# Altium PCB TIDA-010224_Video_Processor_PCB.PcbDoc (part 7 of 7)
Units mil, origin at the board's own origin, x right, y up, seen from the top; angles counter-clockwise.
Board outline 2355.46 x 4164 mil, 10 copper layers (L1-Top Layer, L2-GND, L3-SIG1, L4-GND, L5-PWR, L6-PWR, L7-GND, L8-SIG2, L9-GND, L10-Bottom Layer), stack 62.2 mil thick; 508 components, 274 nets, 3619 pads, 705 vias.
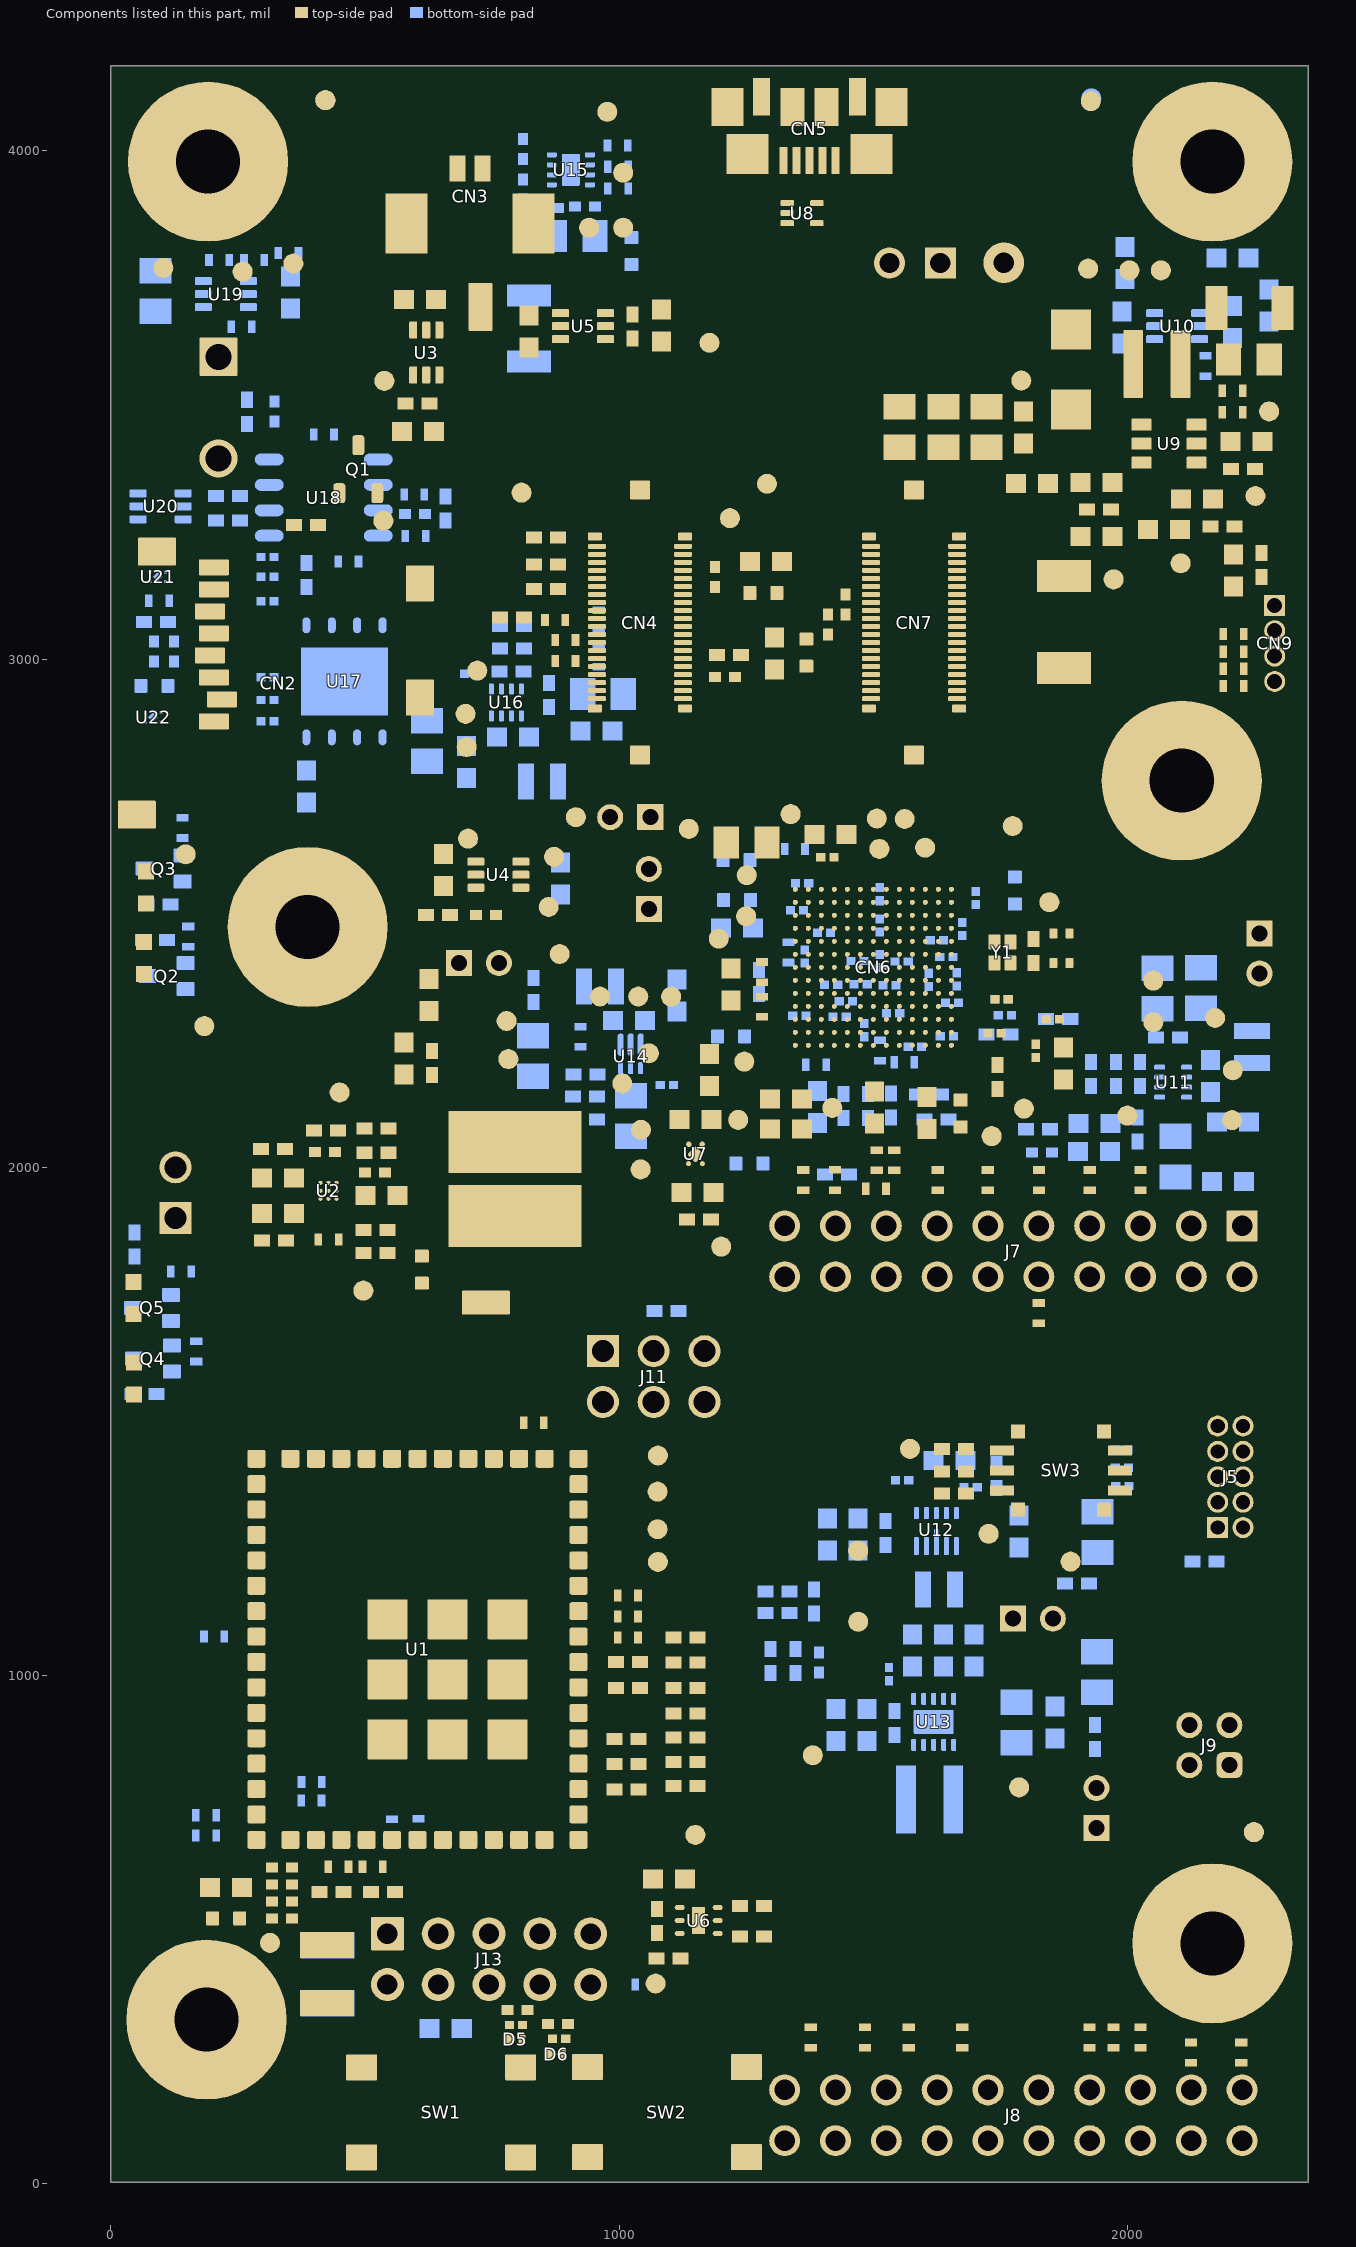
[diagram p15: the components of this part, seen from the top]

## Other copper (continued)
L10-Bottom Layer:
  pour cut-out: 1433.94,2308.27 1430.1,2308.27 1429.23,2307.4 1429.23,2287.84 1431.27,2285.8 1432.85,2285.8 1434.59,2287.54 1434.59,2307.61
  pour cut-out: 1440.91,2370.25 1442.16,2369 1442.16,2317.12 1442.79,2316.49 1442.79,2316.07 1444.13,2314.73 1445.94,2314.73 1445.94,2334.56 1451.6,2340.22 1451.6,2367.41 1448.01,2371 1441.66,2371
  pour cut-out: 1419.62,2368.71 1419.62,2347.59 1418.6,2346.57 1415.64,2346.57 1414.79,2347.42 1414.79,2366.6 1410.43,2370.96 1391.79,2370.96 1387.72,2375.03 1387.72,2393.4 1402,2407.68 1433.91,2407.68 1435.21,2406.39 1433.81,2404.99 1433.81,2375.69 1426.6,2375.69
  pour cut-out: 579.84,2823 579.84,2843.34 612.5,2876 732.77,2876 735,2873.77 735,2864.26 730.74,2860 677.37,2860 674.33,2856.96 674.33,2834.55 666.78,2827 583.84,2827
  pour cut-out: 2056,2073.92 1995.49,2073.92 1994.18,2072.62 1994.18,2004.71 1993.6,2004.14 1833.02,2004.14 1831,2006.16 1831,2102.9 1837,2108.9 1927.51,2108.9 1931.19,2112.57 1931.19,2128.64 1936.37,2133.82 1936.37,2134.51 2050.24,2134.51 2056,2128.75 2055.63,2128.37 2055.63,2074.11
  pour cut-out: 1774.61,2031.93 1731.71,2031.93 1731,2031.21 1728.54,2033.67 1728.54,2061.54 1733.88,2066.88 1762.82,2066.88 1774.61,2055.09
  pour cut-out: 1323.95,2286.36 1316.61,2279.01 1316.61,2139.25 1336.36,2119.5 1449.96,2119.5 1458.46,2128 1477.46,2128 1482,2132.54 1476.46,2138.08 1476.46,2195 1488.19,2206.72 1525.53,2206.72 1532.81,2214 1531.61,2215.2 1531.61,2238.66 1528,2242.28 1527.72,2242 1448.18,2242 1424.18,2266 1400.35,2266 1379.99,2286.36
  pour cut-out: 1816.63,2272.53 1816.63,2224.1 1826.73,2214 1928,2214 1928,2328.03 1924.66,2331.37 1818.37,2331.37 1812,2325 1812,2277.16
  pour cut-out: 412.54,3801.87 412.54,3843.46 402.39,3853.61 275.83,3853.61 261.19,3838.97 261.19,3823.68 261.87,3823 283.23,3823 306.3,3846.07 358.2,3846.07 361.73,3842.54 361.73,3827.37 387.04,3827.37
  pour cut-out: 254.54,3726 210.49,3726 209.95,3725.45 209.95,3764.55 211.22,3763.28 247.01,3763.28 250.73,3759.56 250.73,3729 251.54,3729
  pour cut-out: 1550.84,1045.31 1725.36,1045.31 1725.36,989.94 1554.8,989.94 1554,989.14 1551,992.14 1551,1045
  pour cut-out: 1373,1145.59 1373,1068.76 1383.86,1057.91 1383.86,987.14 1384,987 1383.21,986.21 1371.37,986.21 1366.65,981.48 1258.09,981.48 1253,986.57 1253,1135.53 1264.27,1146.8 1372.99,1146.8
  pour cut-out: 1980.13,2286.52 2005.25,2261.4 2005.25,2185.54 2001.85,2182.14 1951.93,2182.14 1942,2192.07 1942,2248.4
  pour cut-out: 1545,2182 1635.24,2182 1642.24,2175 1642.24,2165.29 1636.46,2159.51 1615.7,2159.51 1610.13,2153.94 1610.13,2103.75 1600.38,2094 1556.81,2094 1544,2106.81 1544,2181
  pour cut-out: 223.01,2536.07 228.58,2530.5 228.58,2384.58 221,2377 26,2377 15,2388 15,2522.37 28.71,2536.07
  pour cut-out: 1164.7,1046.66 1164.7,1126.3 1143,1148 1143,1158.33 1074.33,1158.33 1047.24,1131.24 1047.24,729 1066.56,709.69 1187.61,709.69 1209.63,731.71 1209.63,1033.96 1196.93,1046.66
  pour cut-out: 1561.72,2083 1713.84,2083 1725.78,2071.06 1725.78,2004.26 1671.96,1950.43 1671.96,1904 1664,1896.04 1664,1895.12 1582.05,1895.12 1553.17,1924 1537.94,1924 1537.94,2059.58 1560.72,2082.36
  pour cut-out: 1126.59,2036.55 1126.59,1997.63 1096.8,1967.84 1096.8,1830.26 1046,1779.46 1046,1662.4 1063.4,1645 1242.53,1645 1255,1657.47 1255,1885.41 1296.53,1926.94 1376.94,1926.94 1381.82,1931.82 1381.82,1963.48 1373.15,1972.15 1277.35,1972.15 1265,1984.5 1265,2026.52 1237.85,2053.66 1143.7,2053.66
  pour cut-out: 1129,2035.6 1171.31,2035.6 1180.08,2026.83 1284.93,2026.83 1293.7,2035.6 1293.7,2184.63 1282.33,2196 1277.33,2191 1179.82,2191 1179.82,2162.13 1126.59,2108.9 1126.59,2036.55
  pour cut-out: 66,1836.02 171.01,1836.02 175,1832.03 175,1757.21 164.76,1746.97 78.62,1746.97 64.9,1760.69 64.9,1835.7 65.81,1836.61
  pour cut-out: 96.07,1723.24 96.07,1579.45 113,1562.53 113,1512.9 108.79,1508.69 22.31,1508.69 19,1512 19,1718 24.24,1723.24
  pour cut-out: 2126.96,3664.47 2070.53,3664.47 2050.06,3644 2037.84,3656.22 2011.62,3656.22 2003.37,3664.47 1966.53,3664.47 1962,3669 1962,3753.57 1975.43,3767 2026.95,3767 2077.95,3716 2098.72,3716 2118.46,3696.26 2118.46,3672.97 2126.96,3664.47
  pour cut-out: 383.5,3462 454.5,3462 454.5,3347.05 473.44,3328.12 559.23,3328.12 561.31,3326.03 561.31,3312.5 511.43,3312.5 504.57,3305.64 494.41,3305.64 489.08,3300.3 489.08,3178.08 477,3166 469.19,3166 458.01,3154.82 373.82,3154.82 364.69,3145.69 289.31,3145.69 275.69,3159.31 275.69,3309.33 277.56,3311.2 277.56,3342.33 290.57,3355.34 359.59,3355.34 381.54,3377.3 381.54,3460.04
  pour cut-out: 677.87,3342.89 695.29,3325.46 695.29,3297.11 694.6,3296.41 606.88,3296.41 586,3317.29 586,3344 587.11,3342.89
  pour cut-out: 657.65,3254.42 698.18,3254.42 701,3251.6 701,3242 695.26,3236.26 660.67,3236.26 657.65,3239.29
  text ".Layer_Name" at 514.83,-897.86 h60

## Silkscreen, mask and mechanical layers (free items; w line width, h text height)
Top Overlay:
  drawing of 287 lines, arcs and shapes, not listed
  text "3V3" at 2179,1939 h36
  text "A" at 1077,1756 h40
  text "A" at 1441.49,1525 h40
  text "D" at 637.71,578.04 h40
  text "D" at 1641.71,428.05 h40
  text ".Layer_Name" at 514.83,-897.86 h60
Bottom Overlay:
  circle w6: c2172.67,3681.13 r4.12
  circle w6: c2051,2125 r1.02
  circle w6: c1566.12,973.03 r4.12
  circle w6: c1070.12,2185.94 r4.12
  circle w6: c731.71,2953 r0.7
  circle w6: c271.12,3230.05 r4.12
  circle w6: c304.27,3691 r4.12
  circle w6: c846.98,3934 r4.12
  lines w6: 37,2516 13,2516 11,2514 11,2214 35,2190 175,2190 194,2209 194,2519 157,2519 ; 170,3232 163,3239 178,3239 171,3232 171,3240.91 171,3313 ; 190,3809 296,3809 322,3835 516,3835 ; 193,1064 212,1064 ; 193,1097 214,1097 ; 274,3206 273,3205 273,3149 265,3141 179,3141 164,3126 164,3013 169,3008 270,3008 276,3014 276,3091 281,3096 334,3096 340.7,3102.7 340.7,3201 ; 332,2982 336,2982 340,2978 340,2859 340,2855 ; 630,3341 630,3357 634,3361 661,3361 669,3369 669,3471 ; 1277.29,856 1304.29,829 1513,829 ; 1446,2053 1446,2063 ; 1650,1120 1534,1120 ; 1725.78,2634.78 1725.78,2591.22 1725.78,2464.62 1686,2424.84 1686,2281.23 1686,2248 1624,2186 1479,2186 1459,2206 1459,2264 1448,2275 1333,2275 1323,2285 1308,2300 1308,2701 1302,2707 1280,2729 1280,3152 1293,3165 1759,3165 1788,3136 1788,2697 1727,2636 ; 1899,2122 1894,2127 1871,2127 ; 2024,2244 2023,2244 2006,2261 2006,2564 2031,2589 2184,2589 2205,2568 2205,2432 2205,2303 2198,2296 2198,2269 2189,2260 2149,2260 ; 340,2855 339.31,2855 335,2859.31 344.31,2859.31 340,2855 ; 1534,1120 1540,1126 1540,1114.38 1534.38,1120 1534,1120 ; 1871,2127 1876,2122 1876,2132 1871,2127 ; 15,2861.27 29.27,2847 132,2847 142,2837 142,2751 142,2715.69 157.69,2700 163,2700 230.32,2700 244.83,2714.51 244.83,2840.83 264,2860 269,2865 269,2993.38 263.38,2999 160.52,2999 150,3009.52 150,3106.37 134.59,3121.79 134.59,3194.41 129,3200 116,3200 30.25,3200 15,3184.75 15,2861.27
  text ".Layer_Name" at 514.83,-897.86 h60
Top Paste:
  text ".Layer_Name" at 514.83,-897.86 h60
Bottom Paste:
  text ".Layer_Name" at 514.83,-897.86 h60
Top Solder:
  region: 369.84,1439.93 ccw(c366.43,1439.93) 368.84,1442.35 ccw(c367.24,1440.74) 367.24,1443.01 366.42,1443.01 339.18,1443.01 ccw(c339.18,1440.29) 337.65,1442.54 ccw(c339.59,1440.6) 336.84,1440.6 336.84,1412.72 ccw(c339.26,1412.72) 337.55,1411.01 ccw(c339.96,1413.42) 339.96,1410.01 366.43,1410.01 ccw(c366.43,1413.42) 368.84,1411.01 ccw(c366.43,1413.42) 369.84,1413.42
  region: 370.04,1439.92 ccw(c366.63,1439.92) 369.04,1442.34 ccw(c367.44,1440.73) 367.44,1443 366.62,1443 339.38,1443 ccw(c339.38,1440.28) 337.85,1442.53 ccw(c339.79,1440.59) 337.04,1440.59 337.04,1412.71 ccw(c339.46,1412.71) 337.75,1411 ccw(c340.16,1413.41) 340.16,1410 366.63,1410 ccw(c366.63,1413.41) 369.04,1411 ccw(c366.63,1413.41) 370.04,1413.41
  region: 303,1439.92 ccw(c299.59,1439.92) 302,1442.34 ccw(c300.4,1440.73) 300.4,1443 299.58,1443 272.34,1443 ccw(c272.33,1440.28) 270.8,1442.53 ccw(c272.75,1440.59) 270,1440.59 270,1412.71 ccw(c272.42,1412.71) 270.71,1411 ccw(c273.12,1413.41) 273.12,1410 299.59,1410 ccw(c299.59,1413.41) 302,1411 ccw(c299.59,1413.41) 303,1413.41
  region: 303,1439.59
  region: 1169,1999 1158,1999 1158,2009.42 1166.34,2017.75 1169,2017.75
  region: 1131.39,1999 1142.39,1999 1142.39,2009.42 1134.06,2017.75 1131.39,2017.75
  region: 1168.4,2052.12 1157.4,2052.12 1157.4,2042.67 1165.73,2034.34 1168.4,2034.34
  text ".Layer_Name" at 514.83,-897.86 h60
  text ".Layer_Name" at 514.83,-897.86 h60
Bottom Solder:
  rectangle: 1617.46,1286.68 1630.99,1309.92
  region: 115.93,3149.82 cw(c113.86,3149.82) 113.86,3147.75 112.76,3147.75 98.73,3147.81 98.73,3150.77 101.83,3153.93 105.06,3157.16 113.54,3157.16 cw(c113.54,3154.77) 115.93,3154.77
  region: 115.81,3173.98 ccw(c113.74,3173.98) 113.74,3176.05 112.64,3176.05 98.61,3175.99 98.61,3173.03 101.71,3169.88 104.94,3166.64 113.42,3166.64 ccw(c113.42,3169.03) 115.81,3169.03
  region: 68,3174.04 cw(c70.07,3174.04) 70.07,3176.11 71.17,3176.11 85.2,3176.05 85.2,3173.09 82.11,3169.93 78.87,3166.7 70.39,3166.7 cw(c70.39,3169.09) 68,3169.09
  region: 68.01,3149.89 ccw(c70.08,3149.89) 70.08,3147.82 71.18,3147.82 85.21,3147.88 85.21,3150.84 82.12,3153.99 78.88,3157.23 70.4,3157.23 ccw(c70.4,3154.84) 68.01,3154.84
  region: 58.9,2873.88 ccw(c60.97,2873.88) 60.97,2871.81 62.07,2871.81 76.1,2871.87 76.1,2874.83 73,2877.98 69.77,2881.22 61.29,2881.22 ccw(c61.29,2878.83) 58.9,2878.83
  region: 106.8,2873.91 cw(c104.73,2873.91) 104.73,2871.84 103.63,2871.84 89.6,2871.9 89.6,2874.86 92.7,2878.02 95.93,2881.25 104.41,2881.25 cw(c104.41,2878.86) 106.8,2878.86
  region: 106.8,2898.07 ccw(c104.73,2898.07) 104.73,2900.14 103.63,2900.14 89.6,2900.08 89.6,2897.12 92.7,2893.97 95.93,2890.73 104.41,2890.73 ccw(c104.41,2893.12) 106.8,2893.12
  region: 58.93,2898.09 cw(c61,2898.09) 61,2900.16 62.1,2900.16 76.13,2900.1 76.13,2897.14 73.04,2893.98 69.8,2890.75 61.32,2890.75 cw(c61.32,2893.14) 58.93,2893.14
  text ".Layer_Name" at 514.83,-897.86 h60
Drill Guide:
  text ".Layer_Name" at 514.83,-897.86 h60
M1 Board Outline:
  the board outline again, w8
M2 Board Dimensions:
  drawing of 3885 lines, arcs and shapes, not listed
M3 3D STEP Top:
  text ".Layer_Name" at 514.83,-897.86 h60
M4 3D STEP Bottom:
  drawing of 1284 lines, arcs and shapes, not listed
  text ".Layer_Name" at 514.83,-897.86 h60
M5 Assembly Top:
  circle w6: c1744.37,2441.96 r5.21
  circle w6: c1348.44,3898.63 r5.86
  circle w6: c1181.46,2040.13 r3.62
  circle w6: c443.82,1938.18 r7.21
  circle w6: c996.79,229.14 r14.64
  circle w6: c550.65,227.04 r13.39
  circle w6: c1653.72,2240.05 r15.3
  rectangle: 657.49,4002.09 682.45,4011.21
  lines w6: 301,535.21 301,508.28 369.16,508.28 371.02,510.14 371.02,536.75 302.54,536.75 ; 301.05,536.74 332.92,536.74 ; 301.48,567.63 301.48,540.7 369.64,540.7 371.5,542.56 371.5,569.17 303.02,569.17 ; 301.53,569.16 333.4,569.16 ; 301.65,601.5 301.65,574.57 369.81,574.57 371.67,576.43 371.67,603.04 303.19,603.04 ; 301.64,636.39 301.64,609.46 369.8,609.46 371.66,611.32 371.66,637.93 303.18,637.93 ; 301.7,603.03 333.57,603.03 ; 301.69,637.92 333.56,637.92 ; 370.94,508.07 371.09,508.22 371.09,520 ; 371.42,540.49 371.57,540.64 371.57,552.42 ; 371.59,574.36 371.74,574.51 371.74,586.29 ; 371.58,609.25 371.73,609.4 371.73,621.18 ; 386.87,2041.85 386.87,2017.7 455.31,2017.7 455.31,2042.74 386.87,2042.74 ; 701.42,2510.52 701.42,2483.06 773.26,2483.06 773.26,2511.8 702.7,2511.8 ; 399.25,1922.45 399.25,1987.06 399.51,1987.32 460.54,1987.32 460.54,1922.45 399.25,1922.45 ; 485.38,1977.6 553.05,1977.6 553.05,2002.34 552.58,2002.34 551.34,2003.58 485.38,2003.58 485.38,1977.6 ; 765.04,330.77 765.04,354.97 830.83,354.97 831.06,355.2 831.06,330.77 765.04,330.77 ; 847.3,302.1 913.32,302.1 913.32,326.53 913.09,326.3 847.3,326.3 847.3,302.1 ; 1175.27,2950.54 1242.8,2950.54 1242.8,2951.99 1242.8,2978.08 1175.33,2978.08 1175.27,2978.02 1175.27,2950.54 ; 1175.44,3128.29 1176.89,3128.29 1202.98,3128.29 1202.98,3195.76 1202.92,3195.82 1175.44,3195.82 1175.44,3128.29 ; 1396.99,3034.57 1398.44,3034.57 1424.53,3034.57 1424.53,3102.04 1424.47,3102.1 1396.99,3102.1 1396.99,3034.57 ; 1432.04,3073.81 1432.04,3141.34 1459.52,3141.34 1459.58,3141.28 1459.58,3073.81 1433.49,3073.81 1432.04,3073.81
  lines w10: -354.17,-969.54 6245.83,-969.54 ; -354.17,-766.2 6247.83,-766.2 ; -354.17,-562.87 -354.17,-1172.87 3650.83,-1172.87 6247.83,-1172.87 6247.83,-562.87 -353.67,-562.87 -353.67,-1172.87 1221.83,-1172.87 ; 2110.83,-1172.87 2110.83,-562.87 ; 3377.83,-766.2 3377.83,-562.87 ; 4217.83,-766.2 4217.83,-562.87 ; 4839.83,-1179.37 4839.83,-976.54
  text "C30" at 1196.15,3144.94 h15 r90
  text "C41" at 1452.72,3089.97 h15 r90
  text "C40" at 1417.54,3048.83 h15 r90
  text "C29" at 1188.81,2957.61 h15
  text "C19" at 716.05,2489.93 h15
  text "C8" at 404.96,2022.76 h15
  text "C12" at 500.96,1983.17 h15
  text "U2" at 412.9,1949.85 h15
  text "C3" at 324.94,615.76 h15
  text "C4" at 324.3,581.61 h15
  text "C5" at 323.24,547.25 h15
  text "C6" at 322.61,515.44 h15
  text "C20" at 776.55,335.57 h15
  text "C22" at 858.81,306.9 h15
  text "COMPONENTS MARKED 'DNP' SHOULD NOT BE POPULATED." at 1091.33,-357.87 h60
  text "ASSEMBLY VARIANT:" at 1090.83,-473.37 h60
  text ".VariantName" at 2126.83,-473.37 h60
  text "PCB VIEWED FROM TOP SIDE" at -290.67,-695.04 h60
  text "BOARD #:" at 2185.83,-695.04 h60
  text ".PRJ_Number" at 2731.33,-695.04 h60
  text "REV:" at 3575.83,-695.04 h60
  text "SVN REV:" at 4413.83,-695.04 h60
  text ".VersionControl_RevNumber" at 4919.83,-695.04 h60
  text ".layer_name" at 18,-893 h60
  text "TID #:" at 2185.83,-898.37 h60
  text ".TID" at 2731.33,-898.37 h60
  text ".plot_File_Name" at 379,-1098 h50
  text "PLOT NAME =" at -290.67,-1103.71 h60
  text "GENERATED    :" at 2187.83,-1103.71 h60
  text ".Print_Date" at 3057.33,-1103.71 h60
  text ".Print_Time" at 3786.33,-1103.71 h60
  text "TEXAS INSTRUMENTS" at 5050.83,-1103.71 h60
M6 Assembly Bottom:
  circle w6: c2200.65,823.63 r22.88
  circle w6: c1291.42,77.5 r17.11
  circle w6: c2225.78,1884.79 r20.21
  circle w6: c2156.12,1295.5 r11.42
  lines w6: 1379.17,991.88 1379.17,1060.62 1407.95,1060.62 1407.95,991.03 1380.02,991.03 ; 1797.25,2042.86 1797.25,2014.93 1866.84,2014.93 1866.84,2043.71 1798.1,2043.71 ; 72.38,2982.6 97.8,2982.6 97.8,3048.03 97.39,3048.44 72.38,3048.44 72.38,2982.6 ; 111.77,2982.31 137.19,2982.31 137.19,3047.74 136.78,3048.15 111.77,3048.15 111.77,2982.31 ; 309.48,3455.31 334.9,3455.31 334.9,3520.74 334.49,3521.15 309.48,3521.15 309.48,3455.31 ; 566.6,3274.37 566.6,3299.38 567.01,3299.79 632.44,3299.79 632.44,3274.37 566.6,3274.37 ; 797.46,3889.84 797.46,3957.83 797.46,3959.46 797.83,3959.83 799.46,3959.83 824.75,3959.83 824.75,3888.09 799.21,3888.09 797.46,3889.84 ; 797.67,3968.54 797.67,4036.53 797.67,4038.16 798.04,4038.53 799.67,4038.53 824.96,4038.53 824.96,3966.79 799.42,3966.79 797.67,3968.54 ; 824.47,3874.98 824.84,3874.61 826.47,3874.61 894.46,3874.61 896.21,3876.36 896.21,3901.9 824.47,3901.9 824.47,3876.61 824.47,3874.98 ; 898.17,3877.58 898.54,3877.21 900.17,3877.21 968.16,3877.21 969.91,3878.96 969.91,3904.5 898.17,3904.5 898.17,3879.21 898.17,3877.58
  lines w10: -354.67,-766.7 6247.33,-766.7 ; -352.67,-970.04 6247.33,-970.04 ; 1053.33,-1179.87 1053.33,-977.04 ; 1675.33,-766.7 1675.33,-563.37 ; 2515.33,-766.7 2515.33,-563.37 ; 3782.33,-1173.37 3782.33,-563.37 ; 4671.33,-1173.37 6246.83,-1173.37 6246.83,-563.37 -354.67,-563.37 -354.67,-1173.37 2242.33,-1173.37 6247.33,-1173.37 6247.33,-563.37
  text "C124" at 804.23,3977.01 h15 r270
  text "C123" at 804.23,3899.69 h15 r270
  text "C115" at 960.14,3883.17 h15
  text "C118" at 885.39,3880.89 h15
  text "C130" at 314.76,3460.8 h15 r270
  text "C126" at 626.95,3279.65 h15
  text "C131" at 117.12,2989.63 h15 r270
  text "C134" at 77.66,2988.09 h15 r270
  text "C71" at 1847.03,2022.91 h15
  text "C103" at 1386.57,1000.1 h15 r270
  text "R6" at 142.03,165.17 h0.03
  text "U1" at 142.29,165.48 h0.06
  text "J1" at 142.97,165.58 h0.03
  text "C6" at 142.07,164.79 h0.03 r90
  text "U3" at 142.11,164.82 h0.03
  text "C2" at 142.2,164.98 h0.03
  text "R1" at 142.28,164.91 h0.03
  text "VBAT" at 142.57,164.81 h0.03 r90
  text "Test" at 142.62,164.81 h0.03 r90
  text "IRCUT_N" at 142.66,164.81 h0.03 r90
  text "IRCUT_P" at 142.73,164.81 h0.03 r90
  text "nSLEEP" at 142.79,164.82 h0.03 r90
  text "CN2" at 142.94,164.78 h0.03
  text "COMPONENTS MARKED 'DNP' SHOULD NOT BE POPULATED." at 6039.83,-357.37 h60
  text ".VariantName" at 4995.83,-473.37 h60
  text "ASSEMBLY VARIANT:" at 6034.83,-473.37 h60
  text ".VersionControl_RevNumber" at 973.33,-695.54 h60
  text "SVN REV:" at 1479.33,-695.54 h60
  text "REV:" at 2317.33,-695.54 h60
  text ".PRJ_Number" at 3161.83,-695.54 h60
  text "BOARD #:" at 3707.33,-695.54 h60
  text "PCB VIEWED FROM BOTTOM SIDE" at 6183.83,-695.54 h60
  text ".layer_name" at 5950,-893 h60
  text ".TID" at 3161.83,-898.87 h60
  text "TID #:" at 3707.33,-898.87 h60
  text ".plot_File_Name" at 5529,-1102 h50
  text "TEXAS INSTRUMENTS" at 842.33,-1104.21 h60
  text ".Print_Time" at 2106.83,-1104.21 h60
  text ".Print_Date" at 2835.83,-1104.21 h60
  text "GENERATED    :" at 3705.33,-1104.21 h60
  text "PLOT NAME =" at 6183.83,-1104.21 h60
M9 Title Sheet:
  drawing of 57 lines, arcs and shapes, not listed
  text "1" at 677.67,7997.13 h70
  text "2" at 3173.33,7997.13 h70
  text "3" at 5662.67,7997.13 h70
  text "4" at 8169.34,7997.13 h70
  text "5" at 10668.33,7997.13 h70
  text "6" at 13173.33,7997.13 h70
  text "A" at -478.67,6854.13 h70
  text "A" at 14321.33,6854.13 h70
  text "B" at -478.67,4474.13 h70
  text "B" at 14321.33,4474.13 h70
  text "C" at -478.67,2099.13 h70
  text "C" at 14321.33,2099.13 h70
  text "PROJECT TITLE:" at 11281.33,238.13 h45
  text ".PRJ_Title" at 11331.33,104.8 h70
  text "DESIGNED FOR:" at 11281.33,-62.87 h45
  text ".PRJ_Customer" at 11331.33,-202.87 h70
  text "D" at -478.67,-270.87 h70
  text "D" at 14321.33,-270.87 h70
  text "FILE NAME:" at 11281.33,-362.87 h45
  text ".PCB_File_Name_No_Path" at 11331.33,-482.87 h70
  text "Texas Instruments (TI) and/or its licensors do not warrant the accuracy or completeness of this specification" at 6311.83,-644.71 h45
  text "ENGINEER:" at 11281.33,-652.87 h45
  text "LAYOUT BY:" at 12786.33,-652.87 h45
  text "or any information contained therein. TI and/or its licensors do not warrant that this design will meet" at 6266.84,-757.37 h45
  text ".PRJ_Engineer" at 11331.33,-807.86 h70
  text ".PCB_Layout" at 12836.83,-807.86 h70
  text "the specifications, will be suitable for your application or fit for any particular purpose, or will operate in" at 6266.84,-870.04 h45
  text "ALTIUM DESIGNER VERSION:" at 12786.33,-962.87 h45
  text "an implementation. TI and/or its licensors do not warrant that the design is production worthy. You should" at 6266.84,-982.7 h45
  text "completely validate and test your design implementation to confirm the system functionality for your application." at 6311.83,-1095.37 h45
  text ".print_Scale" at 11331.33,-1096.2 h70
  text ".Application_BuildNumber" at 12836.83,-1096.2 h70
  text "1" at 677.67,-1302.87 h70
  text "2" at 3173.33,-1302.87 h70
  text "3" at 5662.67,-1302.87 h70
  text "4" at 8169.34,-1302.87 h70
  text "5" at 10668.33,-1302.87 h70
  text "6" at 13173.33,-1302.87 h70
M10 Fab Notes:
  drawing of 189 lines, arcs and shapes, not listed
  text "DESIGN INFORMATION" at 12319.85,6316.8 h60
  text "MIN. TRACK WIDTH:" at 11675.29,6184.68 h60
  text "4" at 12771.53,6184.68 h60
  text "MIL" at 12926.29,6184.68 h60
  text "4" at 12769,6066 h60
  text "MIN. CLEARANCE:" at 11675.29,6060.55 h60
  text "MIL" at 12926.29,6060.55 h60
  text "MIN. VIA PAD SIZE:" at 11675.29,5936.43 h60
  text "12" at 12741.54,5936.43 h60
  text "MIL" at 12926.29,5936.43 h60
  text "0.05mm (2MIL)" at 12370.29,5806.53 h60
  text "MINIMUM ANNULAR RING" at 11346.06,5798.3 h60
  text "EXTERNAL" at 13078.29,5798.3 h60
  text "PER" at 11546.06,5688.18 h60
  text "IPC-D-275 CLASS 2 LEVEL C" at 11766.06,5688.17 h60
  text "MIL, HOLES" at 13254.29,5587.7 h60
  text "+/-" at 12861.83,5579.11 h60
  text "+/-" at 13715.83,5579.11 h60
  text "REGISTRATION TOLERANCES:" at 11346.06,5578.05 h60
  text "METAL" at 12545.83,5578.05 h60
  text "5" at 13122.03,5578.05 h60
  text "3" at 13955.03,5578.05 h60
  text "MIL" at 14071.29,5578.05 h60
  text "HOLE SIZE TOLERANCE (UNLESS OTHERWISE SPECIFIED):" at 11346.06,5479.73 h60
  text "+/-" at 13715.83,5476.86 h60
  text "3" at 13955.03,5475.8 h60
  text "MIL" at 14071.29,5475.8 h60
  text "MATERIAL:" at 11271.29,5338.15 h60
  text "FR-4 High Tg" at 12257.73,5209.63 h60
  text "X" at 12113.29,5201.64 h60
  text "FR-408" at 11692.29,5197.12 h60
  text "OTHER" at 13180.29,5197.12 h60
  text "62 MIL (1.6mm) +/-10%" at 12012.39,5054.09 h60
  text "X" at 11892.29,5051.64 h60
  text "THICKNESS:" at 11346.06,5045.87 h60
  text "OTHER" at 13297.29,5045.87 h60
  text "TOLERANCE:" at 11346.06,4907.55 h60
  text "X" at 12194.29,4907.55 h60
  text "ANSI IPC-6012 TYPE 3 CLASS 2" at 12372.31,4907.55 h60
  text "OTHER +/-" at 12372.29,4763.36 h60
  text "BOW & TWIST:" at 11346.06,4618.17 h60
  text "X" at 12194.29,4618.17 h60
  text "ANSI IPC-6012 TYPE 3 CLASS 2" at 12372.31,4618.17 h60
  text "OTHER +/-" at 12372.29,4471.48 h60
  text "DRILLING:" at 11271.29,4340.86 h60
  text "NC_DRILL FILES" at 13032.29,4235.67 h60
  text "REFERENCE:" at 11346.06,4231.73 h60
  text "X" at 12003.29,4231.64 h60
  text "AS SHOWN" at 12181.29,4231.73 h60
  text "X" at 12904.29,4231.73 h60
  text "OTHER" at 13330.29,4089.48 h60
  text "PTH COPPER THICKNESS:" at 11345.74,4085.95 h60
  text "X" at 12484.97,4085.95 h60
  text "20-30 um" at 12612.97,4085.95 h60
  text "BOARD FINISH:" at 11271.29,3938.36 h60
  text "SILKSCREEN:" at 11426.51,3828.23 h60
  text "X" at 12384.29,3828.23 h60
  text "TOP" at 12501.29,3828.23 h60
  text "X" at 12894.29,3828.23 h60
  text "BOTTOM" at 13012.29,3828.23 h60
  text "SILKSCREEN COLOR:" at 11426.51,3673.04 h60
  text "X" at 12383.29,3673.04 h60
  text "WHITE" at 12501.29,3673.04 h60
  text "OTHER" at 13012.29,3673.04 h60
  text "X" at 12514.29,3529.59 h60
  text "GREEN" at 12632.29,3529.59 h60
  text "OTHER" at 13250.29,3529.59 h60
  text "SOLDER RESIST COLOR:" at 11426.51,3522.73 h60
  text "X" at 12514.29,3375.34 h60
  text "MATTE" at 12632.29,3375.34 h60
  text "SEMI-GLOSS" at 13249.83,3374.7 h60
  text "IMMERSION GOLD (ENIG)" at 12332.29,3202.57 h60
  text "ENEPIG" at 13669.83,3195.35 h60
  text "SURFACE FINISH:" at 11271.29,3194.35 h60
  text "X" at 12154.29,3194.35 h60
  text "IMM. TIN/SILVER OR EQUIV" at 11600.83,3057.03 h60
  text "OTHER" at 13032.29,3053.1 h60
  text "ARRAY/PANEL:" at 11271.29,2897.72 h60
  text "CUT AND TRIM PER M1 BOARD OUTLINE" at 12332.29,2889.5 h60
  text "N.C. ROUTE" at 12332.29,2753.53 h60
  text "X" at 13020.29,2753.53 h60
  text "V. SCORE" at 13198.29,2753.53 h60
  text "CERTIFICATION:" at 11271.29,2624.4 h60
  text "MATERIALS AND WORKMANSHIP FOR ALL PCBS" at 11996.29,2624.4 h60
  text "TO MEET OR EXCEED THE REQUIREMENTS OF:" at 11996.29,2530.34 h60
  text "X" at 11633.8,2401.71 h60
  text "ANSI IPC-A-600F CLASS ->" at 11761.79,2401.71 h60
  text "X" at 13409.8,2401.71 h60
  text "2" at 13519.79,2401.71 h60
  text "1" at 13204.79,2400.21 h60
  text "3" at 13873.79,2400.21 h60
  text "X" at 12445.8,2254.02 h60
  text "RoHS" at 12573.79,2254.02 h60
  text "OTHER" at 13218.19,2254.02 h60
  text "PER ORDER" at 13615.25,2254.02 h60
  text "ALL BOARDS MUST MEET OR EXCEED UL94-V0 REQUIREMENTS." at 11298.83,2100.2 h60
  text "PCB MUST BEAR THE UL94V-0 UL REGISTERED MATERIAL ID NUMBER" at 11298.83,1984.13 h60
  text "ADDITIONAL REQUIREMENTS:" at 11271.29,1814.71 h60
  text "MICROSECTION:" at 11346.06,1707.58 h60
  text "YES" at 12251.79,1707.58 h60
  text "REQUIRED" at 13113.29,1563.25 h60
  text "BARE BOARD ELEC. TEST:" at 11346.06,1560.39 h60
  text "NONE" at 12651.79,1560.39 h60
  text "X" at 12995.29,1560.39 h60
  text "PER ORDER" at 13705.29,1560.39 h60
  text "Note:" at 4142.15,1433.9 h150
  text "XX MIL VIAS REQUIRE NON-CONDUCTIVE FILL AND PLANARIZE" at 11514.21,1355.45 h59
  text "1.All vias are tented except on-pad vias and Thermal vias." at 4148.15,1321.9 h150
  text "XX MIL VIAS REQUIRE CONDUCTIVE FILL AND PLANARIZE" at 11522.21,1251.47 h60
  text "2.Vendor may adjust soldermask wherever the soldermask pads are same size(1:1)" at 4148.15,1204.4 h150
  text "OUTER XX MIL TRACES REQUIRE 50 OHM SINGLE-ENDED IMPEDANCE" at 11521.22,1088.09 h58
  text "As per the manufacturing capabilities and all other soldermask pads  / shall not be modified," at 4334.74,966.87 h150
  text "LAYER 2 & 3 (INNER LAYERS) XX MIL WIDE, XX MIL SPACE / TRACES REQUIRE 100 OHM DIFFERENTIAL IMPEDANCE" at 11513.22,852.37 h60
  text "Provided no adjscent copper is exposed and  no conflict is  produced  / with any stated\"Via tenting/covering requirements\"" at 4334.34,732.33 h150
  text "3.Copper thieving is required." at 4141.7,636.5 h150
  text "4.This is an impedance controlled board" at 4137.31,487.14 h150
M11 Gerber Information:
  lines w10: -354.17,-969.54 6245.83,-969.54 ; -354.17,-766.2 6247.83,-766.2 ; -354.17,-562.87 -354.17,-1172.87 3650.83,-1172.87 6247.83,-1172.87 6247.83,-562.87 -353.67,-562.87 -353.67,-1172.87 1221.83,-1172.87 ; 2110.83,-1172.87 2110.83,-562.87 ; 3377.83,-766.2 3377.83,-562.87 ; 4217.83,-766.2 4217.83,-562.87 ; 4839.83,-1179.37 4839.83,-976.54
  text "ALL ARTWORK VIEWED FROM TOP SIDE" at -290.67,-695.04 h60
  text "BOARD #:" at 2185.83,-695.04 h60
  text ".PRJ_Number" at 2731.33,-695.04 h60
  text "REV:" at 3575.83,-695.04 h60
  text "SVN REV:" at 4413.83,-695.04 h60
  text ".VersionControl_RevNumber" at 4919.83,-695.04 h60
  text "LAYER NAME =" at -290.67,-897.86 h60
  text "TID #:" at 2185.83,-898.37 h60
  text ".TID" at 2731.33,-898.37 h60
  text ".plot_File_Name" at 376,-1096 h50
  text "PLOT NAME =" at -290.67,-1103.71 h60
  text "GENERATED    :" at 2187.83,-1103.71 h60
  text ".Print_Date" at 3057.33,-1103.71 h60
  text ".Print_Time" at 3786.33,-1103.71 h60
  text "TEXAS INSTRUMENTS" at 5050.83,-1103.71 h60
M12 Stackup:
  drawing of 607 lines, arcs and shapes, not listed
  text "Layer" at 6541.5,6894.5 h60
  text "Name" at 6951.41,6894.5 h60
  text "Material" at 7991.12,6894.5 h60
  text "Thickness" at 8850.89,6894.5 h60
  text "Constant" at 9500.72,6894.5 h60
  text "Board Layer Stack" at 10070.58,6894.5 h60
  text "1" at 6541.5,6774.5 h60
  text "Top Overlay" at 6951.41,6774.5 h60
  text "2" at 6541.5,6654.5 h60
  text "Top Solder" at 6951.41,6654.5 h60
  text "Solder Resist" at 7991.12,6654.5 h60
  text "0.40mil" at 8850.89,6654.5 h60
  text "3.5" at 9500.72,6654.5 h60
  text "3" at 6541.5,6534.5 h60
  text "L1-Top Layer" at 6951.41,6534.5 h60
  text "Copper" at 7991.12,6534.5 h60
  text "1.76mil" at 8850.89,6534.5 h60
  text "4" at 6541.5,6414.5 h60
  text "Dielectric 2" at 6951.41,6414.5 h60
  text "FR-4 High Tg" at 7991.12,6414.5 h60
  text "3.94mil" at 8850.89,6414.5 h60
  text "4.2" at 9500.72,6414.5 h60
  text "5" at 6541.5,6294.5 h60
  text "L2-GND" at 6951.41,6294.5 h60
  text "Copper" at 7991.12,6294.5 h60
  text "1.18mil" at 8850.89,6294.5 h60
  text "6" at 6541.5,6174.5 h60
  text "Dielectric1" at 6951.41,6174.5 h60
  text "FR-4 High Tg" at 7991.12,6174.5 h60
  text "5.91mil" at 8850.89,6174.5 h60
  text "4.8" at 9500.72,6174.5 h60
  text "7" at 6541.5,6054.5 h60
  text "L3-SIG1" at 6951.41,6054.5 h60
  text "Copper" at 7991.12,6054.5 h60
  text "1.18mil" at 8850.89,6054.5 h60
  text "8" at 6541.5,5934.5 h60
  text "Dielectric 3" at 6951.41,5934.5 h60
  text "FR-4 High Tg" at 7991.12,5934.5 h60
  text "6.89mil" at 8850.89,5934.5 h60
  text "4.2" at 9500.72,5934.5 h60
  text "9" at 6541.5,5814.5 h60
  text "L4-GND" at 6951.41,5814.5 h60
  text "Copper" at 7991.12,5814.5 h60
  text "1.18mil" at 8850.89,5814.5 h60
  text "10" at 6541.5,5694.5 h60
  text "Dielectric 4" at 6951.41,5694.5 h60
  text "FR-4 High Tg" at 7991.12,5694.5 h60
  text "5.91mil" at 8850.89,5694.5 h60
  text "4.2" at 9500.72,5694.5 h60
  text "11" at 6541.5,5574.5 h60
  text "L5-PWR" at 6951.41,5574.5 h60
  text "Copper" at 7991.12,5574.5 h60
  text "1.18mil" at 8850.89,5574.5 h60
  text "12" at 6541.5,5454.5 h60
  text "Dielectric 5" at 6951.41,5454.5 h60
  text "FR-4 High Tg" at 7991.12,5454.5 h60
  text "3.94mil" at 8850.89,5454.5 h60
  text "4.2" at 9500.72,5454.5 h60
  text "13" at 6541.5,5334.5 h60
  text "L6-PWR" at 6951.41,5334.5 h60
  text "Copper" at 7991.12,5334.5 h60
  text "1.18mil" at 8850.89,5334.5 h60
  text "14" at 6541.5,5214.5 h60
  text "Dielectric 6" at 6951.41,5214.5 h60
  text "FR-4 High Tg" at 7991.12,5214.5 h60
  text "5.91mil" at 8850.89,5214.5 h60
  text "4.2" at 9500.72,5214.5 h60
  text "15" at 6541.5,5094.5 h60
  text "L7-GND" at 6951.41,5094.5 h60
  text "Copper" at 7991.12,5094.5 h60
  text "1.18mil" at 8850.89,5094.5 h60
  text "16" at 6541.5,4974.5 h60
  text "Dielectric 7" at 6951.41,4974.5 h60
  text "FR-4 High Tg" at 7991.12,4974.5 h60
  text "6.89mil" at 8850.89,4974.5 h60
  text "4.2" at 9500.72,4974.5 h60
  text "17" at 6541.5,4854.5 h60
  text "L8-SIG2" at 6951.41,4854.5 h60
  text "Copper" at 7991.12,4854.5 h60
  text "1.18mil" at 8850.89,4854.5 h60
  text "18" at 6541.5,4734.5 h60
  text "Dielectric 8" at 6951.41,4734.5 h60
  text "FR-4 High Tg" at 7991.12,4734.5 h60
  text "5.91mil" at 8850.89,4734.5 h60
  text "4.2" at 9500.72,4734.5 h60
  text "19" at 6541.5,4614.5 h60
  text "L9-GND" at 6951.41,4614.5 h60
  text "Copper" at 7991.12,4614.5 h60
  text "1.18mil" at 8850.89,4614.5 h60
  text "20" at 6541.5,4494.5 h60
  text "Dielectric 9" at 6951.41,4494.5 h60
  text "FR-4 High Tg" at 7991.12,4494.5 h60
  text "3.94mil" at 8850.89,4494.5 h60
  text "4.2" at 9500.72,4494.5 h60
  text "21" at 6541.5,4374.5 h60
  text "L10-Bottom Layer" at 6951.41,4374.5 h60
  text "Copper" at 7991.12,4374.5 h60
  text "1.76mil" at 8850.89,4374.5 h60
  text "22" at 6541.5,4254.5 h60
  text "Bottom Solder" at 6951.41,4254.5 h60
  text "Solder Resist" at 7991.12,4254.5 h60
  text "0.40mil" at 8850.89,4254.5 h60
  text "3.5" at 9500.72,4254.5 h60
  text "23" at 6541.5,4134.5 h60
  text "Bottom Overlay" at 6951.41,4134.5 h60
M13 Component Bodies Top:
  text ".Layer_Name" at 514.83,-897.86 h60
M14 Component Bodies Bottom:
  text ".Layer_Name" at 514.83,-897.86 h60
M15 Courtyards Top:
  text ".Layer_Name" at 514.83,-897.86 h60
M16 Courtyards Bottom:
  text ".Layer_Name" at 514.83,-897.86 h60
Drill Drawing:
  circle w10: c7087.55,3222.31 r16.58
  circle w10: c7087.55,3222.31 r27.63
  circle w10: c7087.55,2476.39 r27.63
  lines w10: 3042.2,3504 6796.2,3504 ; 3042.2,3645 6796.2,3645 ; 3042.2,3837.1 6796.2,3837.1 ; 3044,2747.25 6798,2747.25 ; 3044,2947.25 6798,2947.25 ; 3180.2,2212 3180.2,3970.1 ; 5964.2,2212 5964.2,3970.1 ; 6796.2,3250.1 6796.2,3251.1 ; 3042.2,2212 3042.2,3970.1 6796.2,3970.1 6796.2,2212 3042.2,2212 ; 7059.92,2628.34 7115.17,2628.34 7087.55,2573.09 7059.92,2628.34 ; 7059.92,2697.4 7087.55,2711.22 7115.17,2697.4 7101.36,2725.03 7115.17,2752.66 7087.55,2738.85 7059.92,2752.66 7073.73,2725.03 7059.92,2697.4 ; 7059.92,2835.54 7073.73,2835.54 7073.73,2821.72 7101.36,2821.72 7101.36,2835.54 7115.17,2835.54 7115.17,2863.16 7101.36,2863.16 7101.36,2876.98 7073.73,2876.98 7073.73,2863.16 7059.92,2863.16 7059.92,2835.54 ; 7059.92,2946.05 7115.17,2946.05 7115.17,3001.3 7059.92,3001.3 7059.92,2946.05 ; 7059.92,3070.36 7115.17,3070.36 7115.17,3125.62 7059.92,3125.62 7059.92,3070.36 ; 7059.92,3319.01 7059.92,3332.82 7073.73,3346.63 7059.92,3360.44 7059.92,3374.26 7073.73,3374.26 7087.55,3360.44 7101.36,3374.26 7115.17,3374.26 7115.17,3360.44 7101.36,3346.63 7115.17,3332.82 7115.17,3319.01 7101.36,3319.01 7087.55,3332.82 7073.73,3319.01 7059.92,3319.01 ; 7059.92,3443.32 7087.55,3457.14 7115.17,3443.32 7101.36,3470.95 7115.17,3498.58 7087.55,3484.77 7059.92,3498.58 7073.73,3470.95 7059.92,3443.32 ; 7059.92,3581.46 7073.73,3581.46 7087.55,3567.64 7101.36,3581.46 7115.17,3581.46 7101.36,3595.27 7115.17,3609.09 7101.36,3609.09 7087.55,3622.9 7073.73,3609.09 7059.92,3609.09 7073.73,3595.27 7059.92,3581.46 ; 7059.92,3719.59 7087.55,3691.97 7115.17,3719.59 7087.55,3747.22 7059.92,3719.59 ; 7059.92,3830.1 7073.73,3830.1 7087.55,3816.28 7101.36,3830.1 7115.17,3830.1 7101.36,3843.91 7115.17,3857.72 7101.36,3857.72 7087.55,3871.54 7073.73,3857.72 7059.92,3857.72 7073.73,3843.91 7059.92,3830.1 ; 7070.97,3081.42 7104.12,3081.42 7104.12,3114.57 7070.97,3114.57 7070.97,3081.42 ; 7070.97,3454.38 7087.55,3462.66 7104.12,3454.38 7095.84,3470.95 7104.12,3487.53 7087.55,3479.24 7070.97,3487.53 7079.26,3470.95 7070.97,3454.38 ; 7070.97,3835.62 7079.26,3835.62 7087.55,3827.34 7095.84,3835.62 7104.12,3835.62 7095.84,3843.91 7104.12,3852.2 7095.84,3852.2 7087.55,3860.49 7079.26,3852.2 7070.97,3852.2 7079.26,3843.91 7070.97,3835.62
  lines w12: 7009.83,2411.47 10429.35,2411.47 ; 7009.83,3903.31 10429.35,3903.31 ; 7347.69,2287.15 7347.69,4027.63 ; 7679.69,2287.15 7679.69,4027.63 ; 8316.26,2287.15 8316.26,4027.63 ; 8575.4,2287.15 8575.4,4027.63 ; 8950.55,2287.15 8950.55,4027.63 ; 9862.92,2287.15 9862.92,4027.63 ; 7009.83,2287.15 10429.35,2287.15 10429.35,4027.63 7009.83,4027.63 7009.83,2287.15
  text "IMPEDANCE DETAILS:" at 3364.2,4028.1 h150
  text "Symbol" at 7084.42,3940.6 h72
  text "Quantity" at 7384.99,3940.6 h72
  text "Finished Hole Size" at 7716.99,3940.6 h72
  text "Plated" at 8353.55,3940.6 h72
  text "Hole Type" at 8612.69,3940.6 h72
  text "Drill Layer Pair" at 8987.85,3940.6 h72
  text "Hole Tolerance" at 9900.21,3940.6 h72
  text "1" at 3094.2,3884.1 h60
  text "REFERENCE" at 6095.2,3874.1 h60
  text "Differential pairs require 90 ohm+/-10% impedence" at 3270.75,3864.64 h150
  text "245" at 7384.99,3816.28 h60
  text "6.00mil (0.152mm)" at 7716.99,3816.28 h60
  text "PTH" at 8353.55,3816.28 h60
  text "Round" at 8612.69,3816.28 h60
  text "L1-Top Layer - L10-Bottom Layer" at 8987.85,3816.28 h60
  text "LAYER-2" at 6112.7,3707.43 h60
  text "44" at 7384.99,3691.97 h60
  text "7.87mil (0.200mm)" at 7716.99,3691.97 h60
  text "PTH" at 8353.55,3691.97 h60
  text "Round" at 8612.69,3691.97 h60
  text "L1-Top Layer - L10-Bottom Layer" at 8987.85,3691.97 h60
  text "Top Layer differential 5mil width with 6.5mil gap" at 3332.9,3685.2 h120
  text "415" at 7384.99,3567.64 h60
  text "8.00mil (0.203mm)" at 7716.99,3567.64 h60
  text "PTH" at 8353.55,3567.64 h60
  text "Round" at 8612.69,3567.64 h60
  text "L1-Top Layer - L10-Bottom Layer" at 8987.85,3567.64 h60
  text "REFERENCE" at 6086.2,3558 h60
  text "2" at 3095,3545 h60
  text "Differential pairs require 100 ohm+/-10%  impedence" at 3269.75,3527.54 h150
  text "1" at 7384.99,3443.32 h60
  text "10.00mil (0.254mm)" at 7716.99,3443.32 h60
  text "PTH" at 8353.55,3443.32 h60
  text "Round" at 8612.69,3443.32 h60
  text "L1-Top Layer - L10-Bottom Layer" at 8987.85,3443.32 h60
  text "LAYER-2" at 6108.7,3394.19 h60
  text "Top Layer differential 4.0 mil width with 7.5mil gap" at 3353.9,3375.14 h120
  text "10" at 7384.99,3319.01 h60
  text "27.95mil (0.710mm)" at 7716.99,3319.01 h60
  text "PTH" at 8353.55,3319.01 h60
  text "Round" at 8612.69,3319.01 h60
  text "L1-Top Layer - L10-Bottom Layer" at 8987.85,3319.01 h60
  text "LAYER-2 & 4" at 6104.68,3277.44 h60
  text "Sig 1 differential 4mil width with 9mil gap" at 3359.72,3262.82 h120
  text "4" at 7384.99,3194.68 h60
  text "29.53mil (0.750mm)" at 7716.99,3194.68 h60
  text "PTH" at 8353.55,3194.68 h60
  text "Round" at 8612.69,3194.68 h60
  text "L1-Top Layer - L10-Bottom Layer" at 8987.85,3194.68 h60
  text "LAYER-7 & 9" at 6117.82,3136.74 h60
  text "Sig 2 differential 4mil width with 9mil gap" at 3365.54,3126.89 h120
  text "16" at 7384.99,3070.36 h60
  text "31.50mil (0.800mm)" at 7716.99,3070.36 h60
  text "PTH" at 8353.55,3070.36 h60
  text "Round" at 8612.69,3070.36 h60
  text "L1-Top Layer - L10-Bottom Layer" at 8987.85,3070.36 h60
  text "LAYER-9" at 6115,3012 h60
  text "Bottom Layer differential 4.0 mil width with 7.5mil gap" at 3351,3001 h120
  text "13" at 7384.99,2946.05 h60
  text "40.00mil (1.016mm)" at 7716.99,2946.05 h60
  text "PTH" at 8353.55,2946.05 h60
  text "Round" at 8612.69,2946.05 h60
  text "L1-Top Layer - L10-Bottom Layer" at 8987.85,2946.05 h60
  text "40" at 7384.99,2821.72 h60
  text "40.16mil (1.020mm)" at 7716.99,2821.72 h60
  text "PTH" at 8353.55,2821.72 h60
  text "Round" at 8612.69,2821.72 h60
  text "L1-Top Layer - L10-Bottom Layer" at 8987.85,2821.72 h60
  text "REFERENCE" at 6095,2812.25 h60
  text "3" at 3098,2799.5 h60
  text "50 ohm+/-10%  impedence" at 3306,2772.25 h150
  text "8" at 7384.99,2697.4 h60
  text "43.31mil (1.100mm)" at 7716.99,2697.4 h60
  text "PTH" at 8353.55,2697.4 h60
  text "Round" at 8612.69,2697.4 h60
  text "L1-Top Layer - L10-Bottom Layer" at 8987.85,2697.4 h60
  text "LAYER-2" at 6081,2649.25 h60
  text "Top Layer-  5.5 mil width" at 3502.55,2621.8 h120
  text "2" at 7384.99,2573.09 h60
  text "51.18mil (1.300mm)" at 7716.99,2573.09 h60
  text "PTH" at 8353.55,2573.09 h60
  text "Round" at 8612.69,2573.09 h60
  text "L1-Top Layer - L10-Bottom Layer" at 8987.85,2573.09 h60
  text "LAYER-2 & 4" at 6081,2530.25 h60
  text "Sig 1-  4.5 mil width" at 3502.55,2496.8 h120
  text "6" at 7384.99,2448.76 h60
  text "125.98mil (3.200mm)" at 7716.99,2448.76 h60
  text "PTH" at 8353.55,2448.76 h60
  text "Round" at 8612.69,2448.76 h60
  text "L1-Top Layer - L10-Bottom Layer" at 8987.85,2448.76 h60
  text "LAYER-7&9" at 6081,2405.25 h60
  text "Sig 2-  4.5 mil width" at 3502.55,2376.8 h120
  text "804 Total" at 7384.99,2324.44 h60
  text "LAYER-9" at 6081,2266.25 h60
  text "Bot Layer-  5.5 mil width" at 3502.55,2251.8 h120
  text "DRILL TOLERANCE:" at 7713.96,2107.58 h60
  text "FOR 6MIL DRILL +0/-6MIL" at 7712.42,1972.1 h60
  text "FOR 7.87MIL DRILL +0/-7.87MIL" at 7715.42,1876.1 h60
  text "FOR 8MIL DRILL +0/-8MIL" at 7713.42,1770.55 h60
  text "FOR 10MIL DRILL +0/-10MIL" at 7713.42,1677.39 h60
  text "FOR PTH DRILL +/-3MIL" at 7713.42,1579.73 h60
  text ".Layer_Name" at 514.83,-897.86 h60
M17 Embedded Cavity:
  text ".Layer_Name" at 514.83,-897.86 h60
M18 Embedded Assembly:
  text ".Layer_Name" at 514.83,-897.86 h60
M19 Embedded Keepout:
  text ".Layer_Name" at 514.83,-897.86 h60
Mechanical 30:
  drawing of 2914 lines, arcs and shapes, not listed

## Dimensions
0,4167.33 to 2355.46,4167.33 on M2 Board Dimensions
-62.17,-439.37 to 937.83,-439.37 on M2 Board Dimensions
0,3.33 to 0,4167.33 on M2 Board Dimensions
